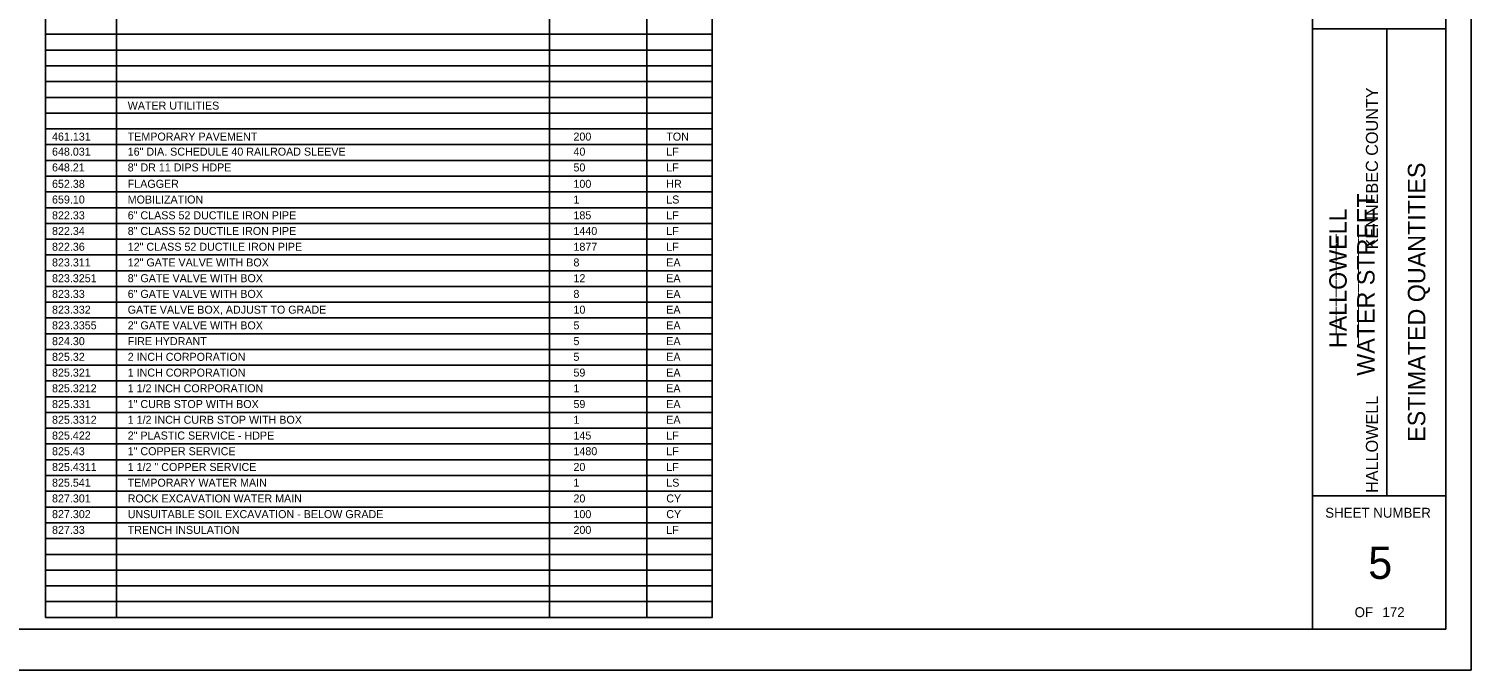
# Model space of a CAD drawing. Extents: x -0.13 to 2.7, y -0.05 to 1.78.
# Drawn here: x 0.896 to 2.698, y -0.051 to 0.75 of the extents above; entities that cross this region are included whole.
import ezdxf

# ---------------------------------------------------------------- set-up
doc = ezdxf.new("R2010")
doc.units = 0
for name, color, linetype in [('ANNOTATION', 7, 'Continuous'), ('BORDER', 7, 'Continuous'), ('BRIDGE_TITLE', 7, 'Continuous'), ('HIGHWAY_TITLE', 7, 'Continuous'), ('PLOT BOUNDARY', 7, 'Continuous')]:
    doc.layers.add(name, color=color, linetype=linetype)

msp = doc.modelspace()

# ---------------------------------------------------------------- linework, layer by layer
at = {"layer": 'BORDER'}
for p, q in [((2.5, 0), (2.5, 1.75)), ((2.6667, 0), (2.6667, 1.75)), ((1.0052, 1.7276), (1.0052, 0.0149)), ((1.5466, 1.7276), (1.5466, 0.0149)), ((1.668, 1.7276), (1.668, 0.0149)), ((0.9167, 0.7433), (1.75, 0.7433)), ((2.5, 0.75), (2.6667, 0.75)), ((2.5932, 0.1667), (2.5932, 0.75)), ((0.9167, 0.7236), (1.75, 0.7236)), ((0.9167, 0.7039), (1.75, 0.7039)), ((0.9167, 0.6842), (1.75, 0.6842)), ((0.9167, 0.6645), (1.75, 0.6645)), ((0.9167, 0.6449), (1.75, 0.6449)), ((0.9167, 0.6252), (1.75, 0.6252)), ((0.9167, 0.6055), (1.75, 0.6055)), ((0.9167, 0.5858), (1.75, 0.5858)), ((0.9167, 0.5661), (1.75, 0.5661)), ((0.9167, 0.5464), (1.75, 0.5464)), ((0.9167, 0.5267), (1.75, 0.5267)), ((0.9167, 0.5071), (1.75, 0.5071)), ((0.9167, 0.4874), (1.75, 0.4874)), ((0.9167, 0.4677), (1.75, 0.4677)), ((0.9167, 0.448), (1.75, 0.448)), ((0.9167, 0.4283), (1.75, 0.4283)), ((0.9167, 0.4086), (1.75, 0.4086)), ((0.9167, 0.3889), (1.75, 0.3889)), ((0.9167, 0.3693), (1.75, 0.3693)), ((0.9167, 0.3496), (1.75, 0.3496)), ((0.9167, 0.3299), (1.75, 0.3299)), ((0.9167, 0.3102), (1.75, 0.3102)), ((0.9167, 0.2905), (1.75, 0.2905)), ((0.9167, 0.2708), (1.75, 0.2708)), ((0.9167, 0.2511), (1.75, 0.2511)), ((0.9167, 0.2315), (1.75, 0.2315)), ((0.9167, 0.2118), (1.75, 0.2118)), ((0.9167, 0.1921), (1.75, 0.1921)), ((0.9167, 0.1724), (1.75, 0.1724)), ((2.5, 0.1667), (2.6667, 0.1667)), ((0.9167, 0.1527), (1.75, 0.1527)), ((0.9167, 0.133), (1.75, 0.133)), ((0.9167, 0.1133), (1.75, 0.1133)), ((0.9167, 0.0936), (1.75, 0.0936)), ((0.9167, 0.074), (1.75, 0.074)), ((0.9167, 0.0543), (1.75, 0.0543)), ((0.9167, 0.0346), (1.75, 0.0346)), ((0, 0), (2.6667, 0))]:
    msp.add_line(p, q, dxfattribs=at)
msp.add_lwpolyline([(0.9167, 1.7473), (1.75, 1.7473), (1.75, 0.0149), (0.9167, 0.0149)], close=True, dxfattribs=at)
at = {"layer": 'PLOT BOUNDARY'}
msp.add_lwpolyline([(-0.1349, -0.051), (2.6984, -0.051), (2.6984, 1.7823), (-0.1349, 1.7823)], close=True, dxfattribs=at)

# ---------------------------------------------------------------- texts
at = {"layer": 'ANNOTATION'}
for s, p in [('WATER UTILITIES', (1.0194, 0.6492)), ('461.131', (0.9248, 0.6105)), ('TEMPORARY PAVEMENT', (1.0194, 0.6105)), ('200', (1.5765, 0.6105)), ('TON', (1.6925, 0.6105)), ('648.031', (0.9248, 0.5917)), ('16" DIA. SCHEDULE 40 RAILROAD SLEEVE', (1.0194, 0.5917)), ('40', (1.5765, 0.5917)), ('LF', (1.6925, 0.5917)), ('648.21', (0.9248, 0.572)), ('8" DR 11 DIPS HDPE', (1.0194, 0.572)), ('50', (1.5765, 0.572)), ('LF', (1.6925, 0.572)), ('652.38', (0.9248, 0.5515)), ('FLAGGER', (1.0194, 0.5515)), ('100', (1.5765, 0.5515)), ('HR', (1.6925, 0.5515)), ('659.10', (0.9248, 0.5319)), ('MOBILIZATION', (1.0194, 0.5319)), ('1', (1.5765, 0.5319)), ('LS', (1.6925, 0.5319)), ('822.33', (0.9248, 0.5122)), ('6" CLASS 52 DUCTILE IRON PIPE', (1.0194, 0.5122)), ('185', (1.5765, 0.5122)), ('LF', (1.6925, 0.5122)), ('822.34', (0.9248, 0.4926)), ('8" CLASS 52 DUCTILE IRON PIPE', (1.0194, 0.4926)), ('1440', (1.5765, 0.4926)), ('LF', (1.6925, 0.4926)), ('822.36', (0.9248, 0.4729)), ('12" CLASS 52 DUCTILE IRON PIPE', (1.0194, 0.4729)), ('1877', (1.5765, 0.4729)), ('LF', (1.6925, 0.4729)), ('823.311', (0.9248, 0.4533)), ('12" GATE VALVE WITH BOX', (1.0194, 0.4533)), ('8', (1.5765, 0.4533)), ('EA', (1.6925, 0.4533)), ('823.3251', (0.9248, 0.4336)), ('8" GATE VALVE WITH BOX', (1.0194, 0.4336)), ('12', (1.5765, 0.4336)), ('EA', (1.6925, 0.4336)), ('823.33', (0.9248, 0.414)), ('6" GATE VALVE WITH BOX', (1.0194, 0.414)), ('8', (1.5765, 0.414)), ('EA', (1.6925, 0.414)), ('823.332', (0.9248, 0.3943)), ('GATE VALVE BOX, ADJUST TO GRADE', (1.0194, 0.3943)), ('10', (1.5765, 0.3943)), ('EA', (1.6925, 0.3943)), ('823.3355', (0.9248, 0.3747)), ('2" GATE VALVE WITH BOX', (1.0194, 0.3747)), ('5', (1.5765, 0.3747)), ('EA', (1.6925, 0.3747)), ('824.30', (0.9248, 0.355)), ('FIRE HYDRANT', (1.0194, 0.355)), ('5', (1.5765, 0.355)), ('EA', (1.6925, 0.355)), ('825.32', (0.9248, 0.3354)), ('2 INCH CORPORATION', (1.0194, 0.3354)), ('5', (1.5765, 0.3354)), ('EA', (1.6925, 0.3354)), ('825.321', (0.9248, 0.3157)), ('1 INCH CORPORATION', (1.0194, 0.3157)), ('59', (1.5765, 0.3157)), ('EA', (1.6925, 0.3157)), ('1 1/2 INCH CORPORATION', (1.0194, 0.2961)), ('825.3212', (0.9248, 0.2961)), ('1', (1.5765, 0.2961)), ('EA', (1.6925, 0.2961)), ('825.331', (0.9248, 0.2764)), ('1" CURB STOP WITH BOX', (1.0194, 0.2764)), ('59', (1.5765, 0.2764)), ('EA', (1.6925, 0.2764)), ('825.3312', (0.9248, 0.2568)), ('1 1/2 INCH CURB STOP WITH BOX', (1.0194, 0.2568)), ('1', (1.5765, 0.2568)), ('EA', (1.6925, 0.2568)), ('825.422', (0.9248, 0.2371)), ('2" PLASTIC SERVICE - HDPE', (1.0194, 0.2371)), ('145', (1.5765, 0.2371)), ('LF', (1.6925, 0.2371)), ('825.43', (0.9248, 0.2175)), ('1" COPPER SERVICE', (1.0194, 0.2175)), ('1480', (1.5765, 0.2175)), ('LF', (1.6925, 0.2175)), ('825.4311', (0.9248, 0.1978)), ('1 1/2 " COPPER SERVICE', (1.0194, 0.1978)), ('20', (1.5765, 0.1978)), ('LF', (1.6925, 0.1978)), ('825.541', (0.9248, 0.1782)), ('TEMPORARY WATER MAIN', (1.0194, 0.1782)), ('1', (1.5765, 0.1782)), ('LS', (1.6925, 0.1782)), ('827.301', (0.9248, 0.1585)), ('ROCK EXCAVATION WATER MAIN', (1.0194, 0.1585)), ('20', (1.5765, 0.1585)), ('CY', (1.6925, 0.1585)), ('827.302', (0.9248, 0.1389)), ('UNSUITABLE SOIL EXCAVATION - BELOW GRADE', (1.0194, 0.1389)), ('100', (1.5765, 0.1389)), ('CY', (1.6925, 0.1389)), ('827.33', (0.9248, 0.1192)), ('TRENCH INSULATION', (1.0194, 0.1192)), ('200', (1.5765, 0.1192)), ('LF', (1.6925, 0.1192))]:
    msp.add_text(s, height=0.01, dxfattribs=at).set_placement(p)
at = {"layer": 'BORDER'}
msp.add_text('ESTIMATED QUANTITIES', height=0.021738, rotation=90, dxfattribs=at).set_placement((2.6411, 0.2342))
for s, height, p in [('SHEET NUMBER', 0.012421, (2.5161, 0.1394)), ('5', 0.0403, (2.5698, 0.063)), ('OF', 0.01242, (2.5528, 0.0152)), ('172', 0.01242, (2.5876, 0.0152))]:
    msp.add_text(s, height=height, dxfattribs=at).set_placement(p)
at = {"layer": 'BRIDGE_TITLE'}
for s, height, p in [('KENNEBEC COUNTY', 0.015119, (2.582, 0.4747)), ('___________', 0.015119, (2.5261, 0.3698)), ('_____________', 0.015119, (2.5541, 0.3532)), ('HALLOWELL', 0.01512, (2.582, 0.1704))]:
    msp.add_text(s, height=height, rotation=90, dxfattribs=at).set_placement(p)
at = {"layer": 'HIGHWAY_TITLE'}
for s, height, p in [('WATER STREET', 0.021738, (2.5777, 0.3168)), ('HALLOWELL', 0.02174, (2.5429, 0.3513))]:
    msp.add_text(s, height=height, rotation=90, dxfattribs=at).set_placement(p)

doc.saveas('drawing.dxf')
